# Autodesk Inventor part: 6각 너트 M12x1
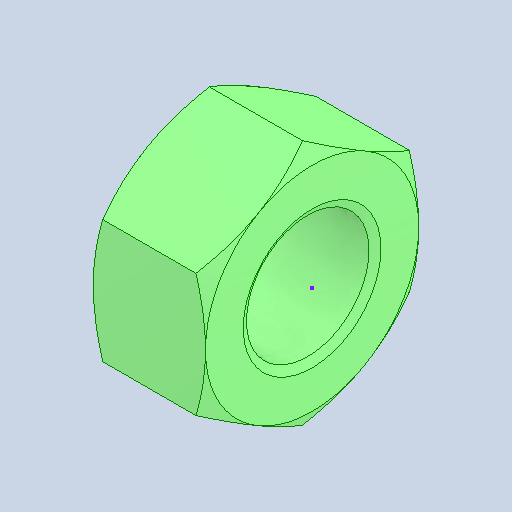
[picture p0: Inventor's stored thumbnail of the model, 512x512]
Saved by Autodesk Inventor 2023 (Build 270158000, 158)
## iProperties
Created: 2025-04
Part Number: 6각 너트 M12x1
Material: 강철, 연강
Description: 6각 너트
Document SubType Name: Modeling
Designer: user
Density: 7.85 g/cm^3
Appearance: 기본값
Author: jhkim
Sending System: Autodesk Inventor 2026
Preprocessor: ST-DEVELOPER v20.1
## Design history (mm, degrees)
node "복구된 형상1"
  node "스케치1"
feature "Solid1"
node "스케치3"
node "솔리드1"
